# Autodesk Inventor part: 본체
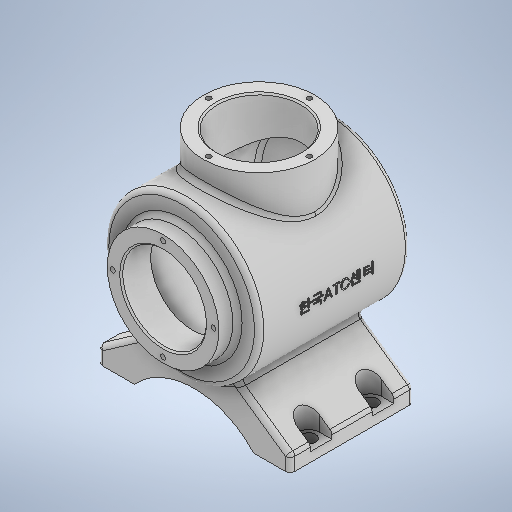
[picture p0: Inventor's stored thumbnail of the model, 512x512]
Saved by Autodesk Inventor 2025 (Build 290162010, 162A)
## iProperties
Created: 2024-07
Part Number: 본체
Material: 일반
Document SubType Name: Modeling
Designer: 학생
Density: 1 g/cm^3
Appearance: 기본값
Author: 학생
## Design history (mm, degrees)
sketch "스케치2"
  geometry: C1 r 50 at (0, 0); 1 further point
  constraints: 1 centre point, 1 coincident
  dimensions: "d2" = 100 diameter of C1
extrude "돌출1" new body sketch "스케치2" stored distance "d3" = 108; taper "d4" = 0 deg
sketch "스케치3"
  geometry: L1 (-50, -54)-(50, -54) reference; L2 (-50, -54)-(-50, 54) reference; L3 (50, -54)-(50, 54) reference; L4 (0, 101.157)-(0, -90.836); A1 r 113 centre (0, 59) between (-50, -42.336) and (50, -42.336); 2 further points
  constraints: 3 point on line, 2 end point, 2 point on circle, 1 centre point, 1 tangent, 1 vertical, 1 vertical alignment
  dimensions: "d5" = 113 radius of A1
revolve "회전1" sketch "스케치3" stored, may be unused: angle "d6" = 90 deg
fillet "모깎기1" dims "d7" = 3
feature "쉘1" dims "d8" = 7
sketch "스케치4"
  geometry: C1 r 36 at (0, 0); 1 further point
  constraints: 1 centre point, 1 coincident
  dimensions: "d9" = 72 diameter of C1
extrude "돌출2" join sketch "스케치4" distance "d10" = 12; taper "d11" = 0 deg
sketch "스케치5"
  geometry: C1 r 36 at (0, 0) reference; 2 further points
  constraints: 1 coincident
hole "구멍1" sketch "스케치5" at (0, 0) diameter "d12" = 54; stored, may be unused: countersink angle "d16" = 90 deg, drill point angle "d18" = 0 deg; dims "d13" = 8, "d14" = 4, "d15" = 2, "d17" = 19
fillet "모깎기2" dims "d19" = 3
fillet "모깎기3" dims "d20" = 3
chamfer "모따기1" distance "d21" = 1; stored, may be unused: second distance "d22" = 2, angle "d23" = 45 deg
sketch "스케치6"
  geometry: L1 (-62, -77)-(62, -77); L2 (-62, -77)-(-62, -67); L3 (-62, -67)-(-26.694, -42.278); L4 (62, -77)-(62, -67); L5 (62, -67)-(26.694, -42.278); L6 (0, 62.14)-(0, -91.323); A1 r 50 centre (0, 0) between (-26.694, -42.278) and (26.694, -42.278) reference; A2 r 52.096 centre (0, -112.096) between (38.5, -77) and (-38.5, -77); 4 further points
  constraints: 12 end point, 5 point on circle, 3 point on line, 3 vertical, 2 equal length, 2 midpoint, 1 centre point, 1 horizontal, 1 vertical alignment, 1 other
  dimensions: "d24" = 10 distance of L1.start L2.end; "d25" = 77 distance from line of point (0, 0) L1; "d26" = 55 deg angle of L4 L5; "d27" = 17 distance of point (0, -77) point (0, -60); "d28" = 77 distance of A2.start A2.end; "d29" = 124 distance from line of point (-62, -72) L4
extrude "돌출3" join sketch "스케치6" distance "d30" = 46; taper "d31" = 0 deg; dims "d32" = 34, "d33" = 0
fillet "모깎기4" dims "d34" = 3
fillet "모깎기5" dims "d35" = 3
fillet "모깎기6" dims "d36" = 3
node "작업 평면1"
sketch "스케치7"
  geometry: L1 (-2.5, 100)-(-74.5, 100) reference; C1 r 36 at (-38.5, 38); 1 further point
  constraints: 1 centre point, 1 vertical alignment
  dimensions: "d39" = 72 diameter of C1; "d40" = 62 distance from line of L1 C1.centre
extrude "돌출4" join sketch "스케치7" stored distance "d41" = 46; taper "d42" = 0 deg
sketch "스케치8"
  geometry: C1 r 36 at (0, 0) reference; 2 further points
  constraints: 1 coincident
hole "구멍2" sketch "스케치8" at (0, 0) diameter "d43" = 54; stored, may be unused: countersink angle "d47" = 90 deg, drill point angle "d49" = 0 deg; dims "d44" = 6, "d45" = 4, "d46" = 2, "d48" = 50
chamfer "모따기2" distance "d50" = 1; stored, may be unused: second distance "d51" = 2, angle "d52" = 45 deg
node "작업 평면2"
sketch "스케치9"
  geometry: L1 (23.5, 3)-(23.5, 77) reference; L2 (15.5, 27)-(23.5, 27); L3 (20.5, 0)-(0, 0) reference; L4 (15.5, 13)-(23.5, 13); L5 (-100.5, 77)-(-100.5, 3) reference; L6 (-100.5, 40)-(23.5, 40); L7 (-38.5, -15.146)-(-38.5, 101.944); L8 (15.5, 67)-(23.5, 67); L9 (15.5, 53)-(23.5, 53); L10 (-92.5, 13)-(-100.5, 13); L11 (-92.5, 27)-(-100.5, 27); L12 (-92.5, 53)-(-100.5, 53); L13 (-92.5, 67)-(-100.5, 67); A1 r 7 centre (15.5, 20) between (15.5, 27) and (15.5, 13); A2 r 7 centre (15.5, 60) between (15.5, 67) and (15.5, 53); A3 r 7 centre (-92.5, 20) between (-92.5, 13) and (-92.5, 27); A4 r 7 centre (-92.5, 60) between (-92.5, 53) and (-92.5, 67); 8 further points
  constraints: 20 end point, 15 symmetric about line, 8 point on circle, 4 centre point, 3 midpoint, 3 point on line, 1 horizontal, 1 perpendicular, 1 tangent, 1 vertical, 3 other
  dimensions: "d54" = 20 distance from line of L3 A1.centre; "d56" = 14 distance between parallel lines of L4 L2; "d57" = 8 distance from line of A1.centre L1; "d58" = 14 diameter of A1
extrude "돌출5" cut sketch "스케치9" stored distance "d59" = 10; taper "d60" = 0 deg
sketch "스케치10"
  geometry: A1 r 7 centre (15.5, -60) between (15.5, -53) and (15.5, -67) reference; A2 r 7 centre (15.5, -20) between (15.5, -13) and (15.5, -27) reference; A3 r 7 centre (-92.5, -60) between (-92.5, -67) and (-92.5, -53) reference; A4 r 7 centre (-92.5, -20) between (-92.5, -27) and (-92.5, -13) reference; 5 further points
  constraints: 4 coincident
hole "구멍3" sketch "스케치10" at (15.5, -60), (15.5, -20), (-92.5, -60), (-92.5, -20) diameter "d61" = 9; stored, may be unused: countersink angle "d65" = 90 deg, drill point angle "d67" = 0 deg; dims "d62" = 6, "d63" = 4, "d64" = 2, "d66" = 50
fillet "모깎기7" dims "d68" = 3
sketch "스케치11"
  geometry: C1 r 36 at (0, 0) reference; 2 further points
  constraints: 1 vertical alignment
  dimensions: "d69" = 32.5 distance of C1.centre point (0, 32.5)
hole "구멍4" sketch "스케치11" at (0, 32.5) diameter "d70" = 3.242; stored, may be unused: countersink angle "d74" = 90 deg, drill point angle "d76" = 120 deg; dims "d71" = 8, "d72" = 4, "d73" = 2, "d75" = 10
sketch "스케치12"
  geometry: 2 further points
  constraints: 1 vertical alignment
  dimensions: "d77" = 32.5 distance of point (0, 0) point (0, 32.5)
hole "구멍5" sketch "스케치12" at (0, 32.5) diameter "d78" = 3.242; stored, may be unused: countersink angle "d82" = 90 deg, drill point angle "d84" = 120 deg; dims "d79" = 8, "d80" = 4, "d81" = 2, "d83" = 10
node "작업 평면3"
sketch "스케치13"
  geometry: L1 (36, 66)-(-36, 66) reference; 2 further points
  constraints: 1 vertical alignment, 1 other
  dimensions: "d92" = 62 distance from line of L1 point (0, 4)
feature "엠보싱1" sketch "스케치13" dims "d93" = 0.5, "d94" = 0
fillet "모깎기8" dims "d95" = 3
node "솔리드1"
pattern_circular "원형 패턴1" dims angle "d86" = 360 deg
pattern_circular "원형 패턴2" dims angle "d89" = 360 deg
feature "A9D066F2-1C7D-4E18-AEED-F7BC21143FA4" dims "d12" = 54, "d13" = 8, "d14" = 4, "d15" = 2, "d16" = 90 deg, "d17" = 19, "d18" = 0
other parameters: "d37" = -142, "d53" = -6, "d91" = 124.25
